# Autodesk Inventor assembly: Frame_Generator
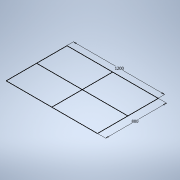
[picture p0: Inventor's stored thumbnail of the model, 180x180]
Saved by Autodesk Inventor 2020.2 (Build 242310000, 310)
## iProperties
Created: 2020-01
Part Number: Frame_Generator
Document SubType Name: Assembly
Designer: thira
Author: thira
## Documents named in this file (2)
- F:\99.โปรแกรมอัดหน้าจอ\Synergysoft\FRAME\Frame_Generator.iam
- F:\99.โปรแกรมอัดหน้าจอ\Synergysoft\FRAME\Structure.ipt
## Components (1 placed, 1 different names)
1. Structure:1
